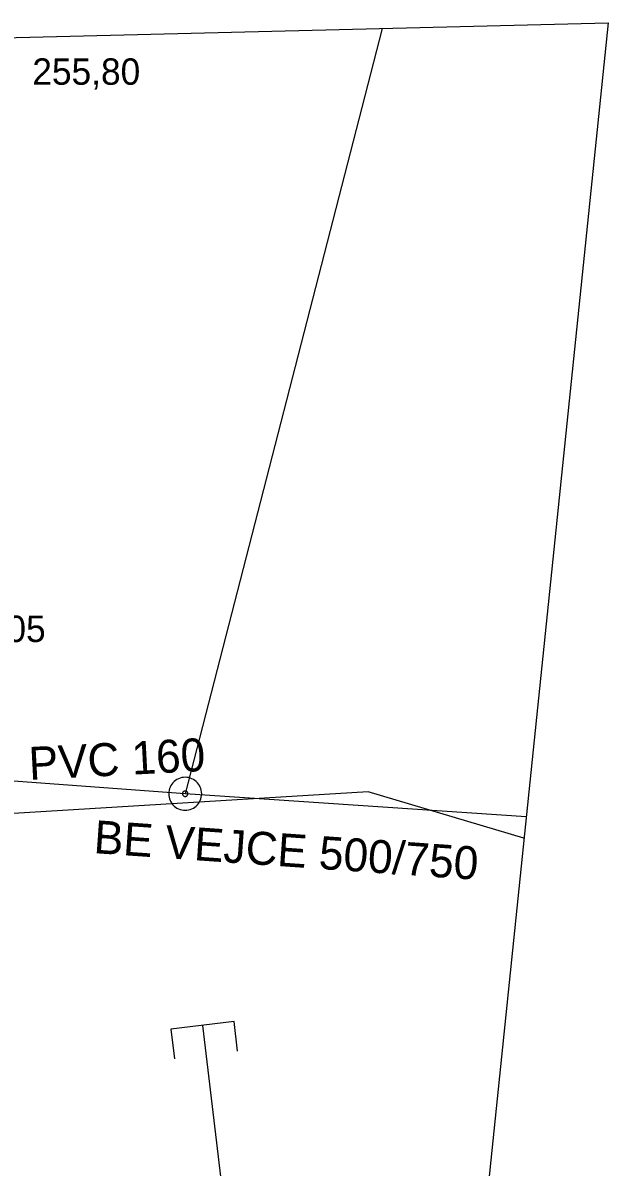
# Model space of a CAD drawing. Extents: x -725807 to -725723.1, y -978165.9 to -978101.2.
# Drawn here: x -725740.87 to -725723.13, y -978135.86 to -978101.16 of the extents above; entities that cross this region are included whole.
import ezdxf

# ---------------------------------------------------------------- set-up
doc = ezdxf.new("R2010")
doc.units = 0
for name, color, linetype in [('Vrstva 1', 7, 'Continuous'), ('Vrstva 14', 7, 'Continuous'), ('Vrstva 17', 7, 'Continuous'), ('Vrstva 31', 7, 'Continuous')]:
    doc.layers.add(name, color=color, linetype=linetype)

msp = doc.modelspace()

# ---------------------------------------------------------------- linework, layer by layer
at = {"layer": 'Vrstva 1'}
msp.add_lwpolyline([(-725807.01, -978138.838), (-725796.543, -978102.971), (-725723.134, -978101.157), (-725729.135, -978159.354), (-725758.583, -978165.913), (-725792.915, -978158.237)], close=True, dxfattribs=at)
at = {"layer": 'Vrstva 14'}
for points in [[(-725729.984, -978101.326), (-725735.954, -978124.533)], [(-725735.954, -978124.533), (-725748.41, -978123.62)], [(-725725.617, -978125.232), (-725735.954, -978124.533)], [(-725735.431, -978131.559), (-725733.245, -978149.864), (-725732.85, -978160.181)]]:
    msp.add_lwpolyline(points, dxfattribs=at)
at = {"layer": 'Vrstva 17'}
msp.add_lwpolyline([(-725725.684, -978125.879), (-725730.408, -978124.478), (-725745.136, -978125.378)], dxfattribs=at)
at = {"layer": 'Vrstva 31'}
for points in [[(-725735.455, -978124.533), (-725735.458, -978124.481), (-725735.466, -978124.429), (-725735.48, -978124.379), (-725735.497, -978124.33), (-725735.522, -978124.283), (-725735.551, -978124.239), (-725735.583, -978124.199), (-725735.62, -978124.162), (-725735.661, -978124.129), (-725735.705, -978124.1), (-725735.752, -978124.076), (-725735.801, -978124.058), (-725735.85, -978124.044), (-725735.902, -978124.036), (-725735.955, -978124.033), (-725736.007, -978124.036), (-725736.059, -978124.044), (-725736.11, -978124.058), (-725736.157, -978124.076), (-725736.205, -978124.1), (-725736.249, -978124.129), (-725736.289, -978124.162), (-725736.326, -978124.199), (-725736.36, -978124.239), (-725736.387, -978124.283), (-725736.412, -978124.33), (-725736.431, -978124.379), (-725736.443, -978124.429), (-725736.451, -978124.481), (-725736.455, -978124.533), (-725736.451, -978124.585), (-725736.443, -978124.637), (-725736.431, -978124.688), (-725736.412, -978124.736), (-725736.387, -978124.783), (-725736.36, -978124.827), (-725736.326, -978124.868), (-725736.289, -978124.905), (-725736.249, -978124.938), (-725736.205, -978124.966), (-725736.157, -978124.99), (-725736.11, -978125.009), (-725736.059, -978125.022), (-725736.007, -978125.03), (-725735.955, -978125.033), (-725735.902, -978125.03), (-725735.85, -978125.022), (-725735.801, -978125.009), (-725735.752, -978124.99), (-725735.705, -978124.966), (-725735.661, -978124.938), (-725735.62, -978124.905), (-725735.583, -978124.868), (-725735.551, -978124.827), (-725735.522, -978124.783), (-725735.497, -978124.736), (-725735.48, -978124.688), (-725735.466, -978124.637), (-725735.458, -978124.585), (-725735.455, -978124.533)], [(-725735.872, -978124.533), (-725735.872, -978124.524), (-725735.875, -978124.516), (-725735.877, -978124.508), (-725735.88, -978124.5), (-725735.884, -978124.492), (-725735.889, -978124.485), (-725735.894, -978124.478), (-725735.899, -978124.472), (-725735.907, -978124.467), (-725735.914, -978124.462), (-725735.921, -978124.458), (-725735.929, -978124.455), (-725735.938, -978124.453), (-725735.946, -978124.451), (-725735.955, -978124.451), (-725735.963, -978124.451), (-725735.972, -978124.453), (-725735.98, -978124.455), (-725735.988, -978124.458), (-725735.995, -978124.462), (-725736.002, -978124.467), (-725736.01, -978124.472), (-725736.016, -978124.478), (-725736.022, -978124.485), (-725736.026, -978124.492), (-725736.029, -978124.5), (-725736.032, -978124.508), (-725736.034, -978124.516), (-725736.037, -978124.524), (-725736.037, -978124.533), (-725736.037, -978124.542), (-725736.034, -978124.55), (-725736.032, -978124.558), (-725736.029, -978124.566), (-725736.026, -978124.574), (-725736.022, -978124.581), (-725736.016, -978124.588), (-725736.01, -978124.594), (-725736.002, -978124.6), (-725735.995, -978124.604), (-725735.988, -978124.608), (-725735.98, -978124.611), (-725735.972, -978124.613), (-725735.963, -978124.615), (-725735.955, -978124.615), (-725735.946, -978124.615), (-725735.938, -978124.613), (-725735.929, -978124.611), (-725735.921, -978124.608), (-725735.914, -978124.604), (-725735.907, -978124.6), (-725735.899, -978124.594), (-725735.894, -978124.588), (-725735.889, -978124.581), (-725735.884, -978124.574), (-725735.88, -978124.566), (-725735.877, -978124.558), (-725735.875, -978124.55), (-725735.872, -978124.542), (-725735.872, -978124.533)], [(-725734.471, -978131.443), (-725736.39, -978131.673)], [(-725734.364, -978132.338), (-725734.471, -978131.443)], [(-725736.39, -978131.673), (-725736.283, -978132.567)]]:
    msp.add_lwpolyline(points, dxfattribs=at)

# ---------------------------------------------------------------- texts
at = {"layer": 'Vrstva 1'}
for s, p in [('255,80', (-725740.589, -978103.033)), ('255,05', (-725743.457, -978119.932))]:
    msp.add_text(s, height=0.8, dxfattribs=at).set_placement(p)
for s, rotation, p in [('PVC 160 ', 3, (-725740.672, -978124.118)), ('BE VEJCE 500/750', 356, (-725738.746, -978126.332))]:
    msp.add_text(s, height=1, rotation=rotation, dxfattribs=at).set_placement(p)

doc.saveas('drawing.dxf')
